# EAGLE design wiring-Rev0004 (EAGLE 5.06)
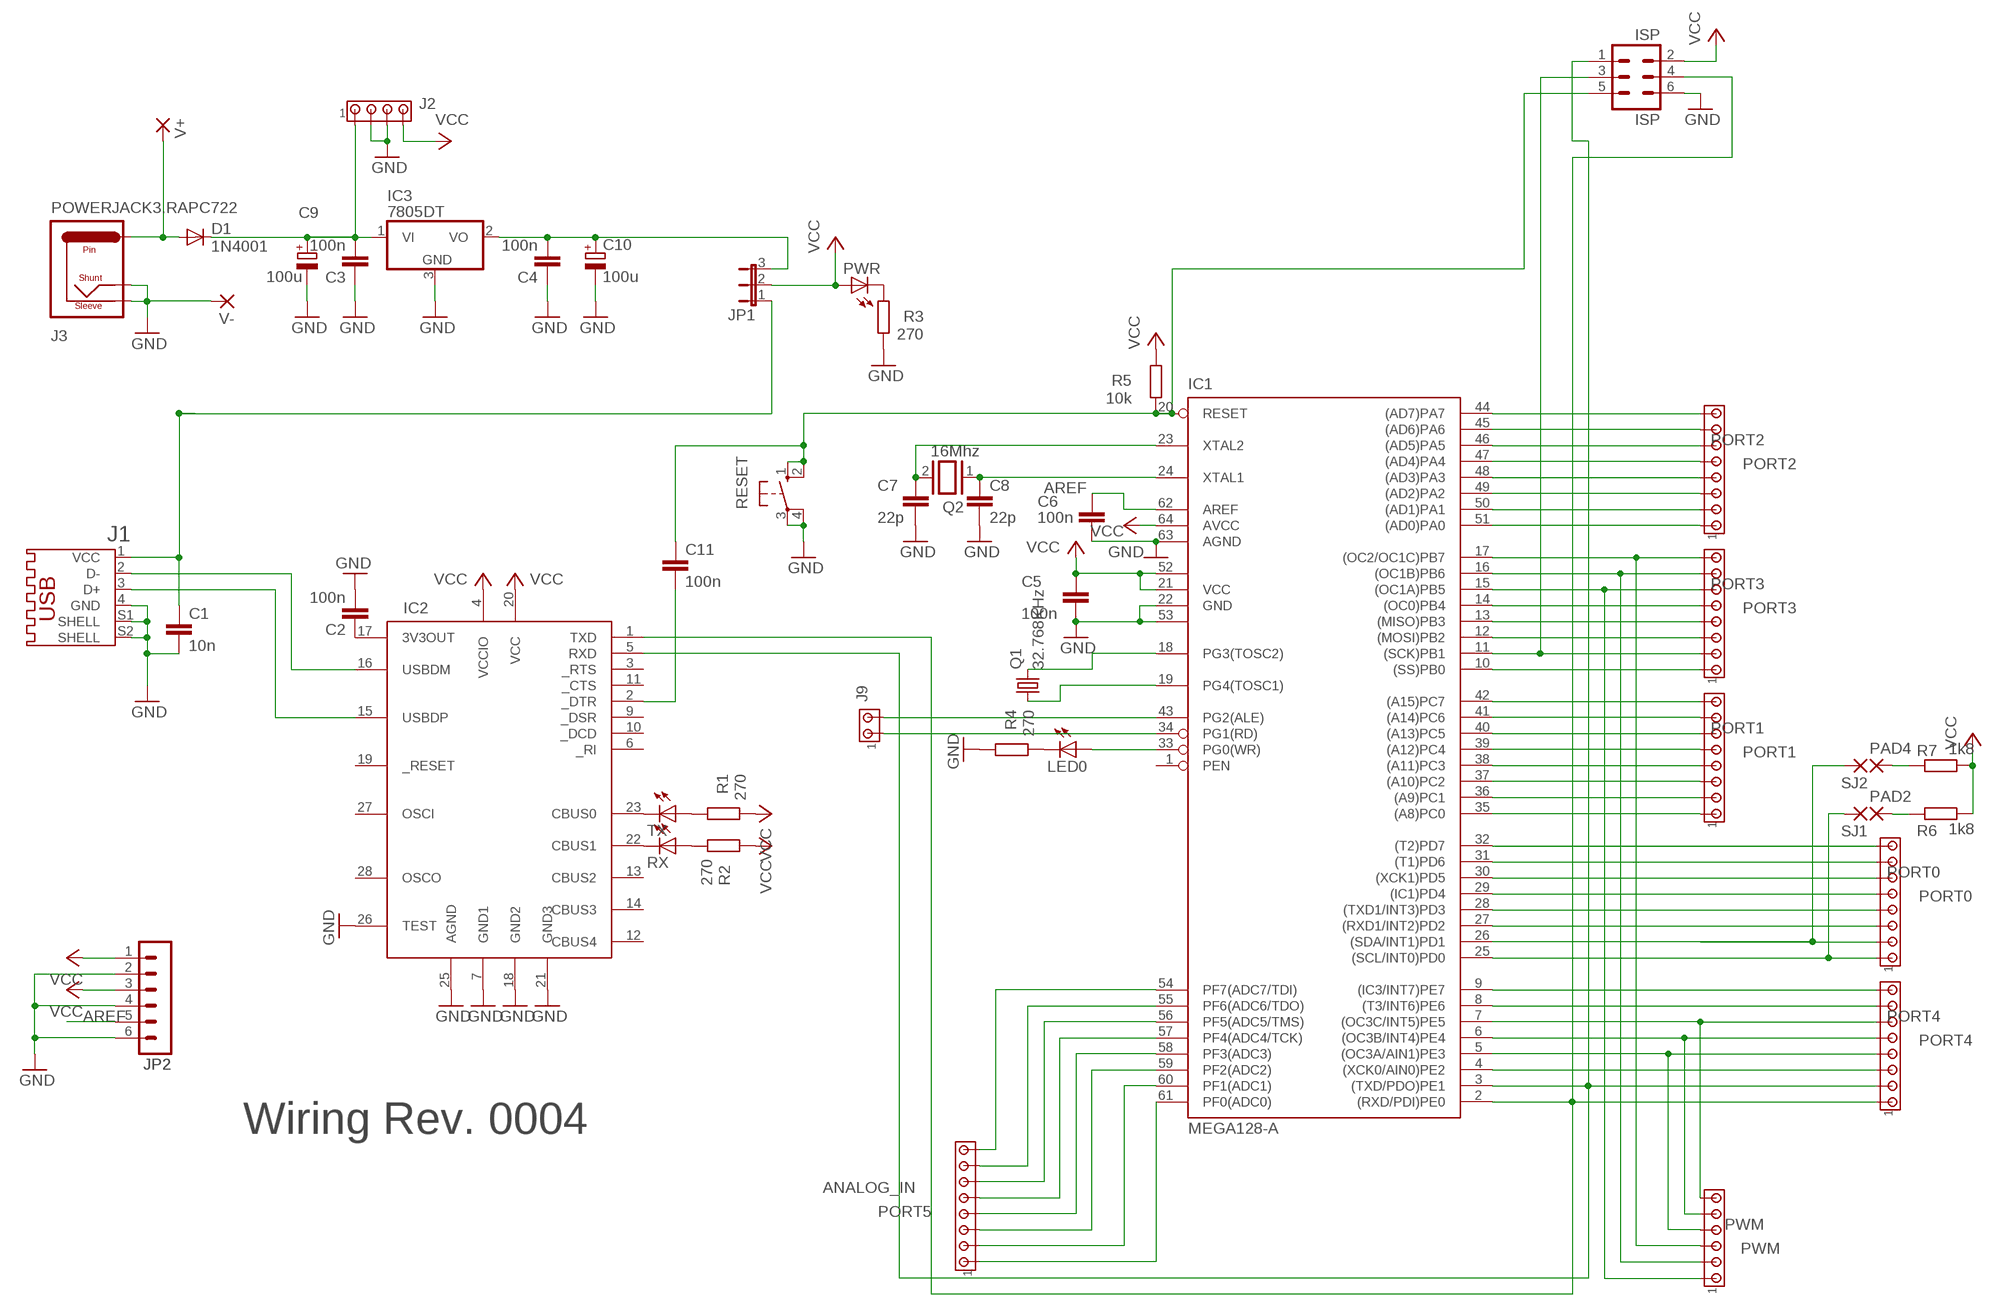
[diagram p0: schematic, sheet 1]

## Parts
ANALOG_IN  PORT5  MTA08-100  [10X08MTA]
C1  10n  C-EUC1206K  [C1206K]
C2  100n  C-EUC1206K  [C1206K]
C3  100n  C-EUC1206K  [C1206K]
C4  100n  C-EUC1206K  [C1206K]
C5  100n  C-EUC1206K  [C1206K]
C6  100n  C-EUC1206K  [C1206K]
C7  22p  C-EUC1206K  [C1206K]
C8  22p  C-EUC1206K  [C1206K]
C9  100u  CPOL-EU153CLV-0807  [153CLV-0807]
C10  100u  CPOL-EU153CLV-0807  [153CLV-0807]
C11  100n  C-EUC1206K  [C1206K]
D1  1N4001  DIODE-SOD106-R  [SOD106-R]
IC1  MEGA128-A  [TQFP64]
IC2  FT232RL  [SSOP28DB]
IC3  7805DT  [TO252]
ISP  ISP  MA03-2  [MA03-2]
J1  USB-CON-B  [USB-B-RECEPTACLE]
J2  MTA04-100  [10X04MTA]
J3  POWERJACK3.RAPC722  [SC.RAPC722]
J9  MTA02-100  [10X02MTA]
JP1  JP2E  [JP2]
JP2  MA06-1  [MA06-1]
LED0  LEDCHIPLED_1206  [CHIPLED_1206]
PAD2  1,6/0,8  [1,6/0,8]
PAD4  1,6/0,8  [1,6/0,8]
PORT0  PORT0  MTA08-100  [10X08MTA]
PORT1  PORT1  MTA08-100  [10X08MTA]
PORT2  PORT2  MTA08-100  [10X08MTA]
PORT3  PORT3  MTA08-100  [10X08MTA]
PORT4  PORT4  MTA08-100  [10X08MTA]
PWM  PWM  MTA06-100  [10X06MTA]
PWR  LEDCHIPLED_1206  [CHIPLED_1206]
Q1  32.768KHz  CRYTALMM20SS  [MM20SS]
Q2  16Mhz  XTAL/S  [QS]
R1  270  R-EU_R1206W  [R1206W]
R2  270  R-EU_R1206W  [R1206W]
R3  270  R-EU_R1206W  [R1206W]
R4  270  R-EU_R1206W  [R1206W]
R5  10k  R-EU_R1206W  [R1206W]
R6  1k8  R-EU_R1206W  [R1206W]
R7  1k8  R-EU_R1206W  [R1206W]
RESET  10-XX  [B3F-10XX]
RX  LEDCHIPLED_1206  [CHIPLED_1206]
SJ1  1,6/0,8  [1,6/0,8]
SJ2  1,6/0,8  [1,6/0,8]
TX  LEDCHIPLED_1206  [CHIPLED_1206]
V+  1,6/0,8  [1,6/0,8]
V-  1,6/0,8  [1,6/0,8]

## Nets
AREF: C6.1 IC1.62(AREF) JP2.5
GND: C1.2 C2.2 C3.1 C4.1 C5.2 C6.2 C7.2 C8.2 C9.- C10.- IC1.22(GND) IC1.53(GND1) IC1.63(AGND) IC2.7(GND1) IC2.18(GND2) IC2.21(GND3) IC2.25(AGND) IC2.26(TEST) IC3.3(GND) ISP.6 J1.4(GND) J1.S1(SHELL) J1.S2(SHELL) J2.2 J2.3 J3.SHUNT J3.SLEEVE JP2.2 JP2.4 JP2.6 R3.1 R4.2 RESET.3(P) RESET.4(P1) V-.1(P)
N$1: IC2.16(USBDM) J1.2(D-)
N$2: IC2.15(USBDP) J1.3(D+)
N$3: C2.1 IC2.17(3V3OUT)
N$4: IC2.23(CBUS0) TX.C
N$5: IC2.22(CBUS1) RX.C
N$6: R1.2 TX.A
N$7: C1.1 J1.1(VCC) JP1.1
N$8: R2.1 RX.A
N$9: PAD4.1(P) R7.2
N$10: PAD2.1(P) R6.2
N$11: C11.2 IC2.2(_DTR)
N$15: C7.1 IC1.23(XTAL2) Q2.2
N$16: C8.1 IC1.24(XTAL1) Q2.1
N$17: IC1.2((RXD/PDI)PE0) IC2.1(TXD) ISP.4 PORT4.1
N$18: IC1.3((TXD/PDO)PE1) IC2.5(RXD) ISP.1 PORT4.2
N$19: IC1.19(PG4(TOSC1)) Q1.1
N$21: IC1.51((AD0)PA0) PORT2.1
N$22: IC1.50((AD1)PA1) PORT2.2
N$23: IC1.49((AD2)PA2) PORT2.3
N$24: IC1.48((AD3)PA3) PORT2.4
N$25: IC1.47((AD4)PA4) PORT2.5
N$26: IC1.46((AD5)PA5) PORT2.6
N$27: IC1.45((AD6)PA6) PORT2.7
N$28: IC1.44((AD7)PA7) PORT2.8
N$29: IC1.14((OC0)PB4) PORT3.5
N$30: IC1.41((A14)PC6) PORT1.7
N$31: IC1.40((A13)PC5) PORT1.6
N$32: IC1.39((A12)PC4) PORT1.5
N$33: IC1.38((A11)PC3) PORT1.4
N$34: IC1.37((A10)PC2) PORT1.3
N$35: IC1.36((A9)PC1) PORT1.2
N$36: IC1.35((A8)PC0) PORT1.1
N$37: ANALOG_IN.1 IC1.61(PF0(ADC0))
N$38: ANALOG_IN.2 IC1.60(PF1(ADC1))
N$39: ANALOG_IN.3 IC1.59(PF2(ADC2))
N$40: ANALOG_IN.4 IC1.58(PF3(ADC3))
N$41: ANALOG_IN.5 IC1.57(PF4(ADC4/TCK))
N$42: ANALOG_IN.6 IC1.56(PF5(ADC5/TMS))
N$43: ANALOG_IN.7 IC1.55(PF6(ADC6/TDO))
N$44: ANALOG_IN.8 IC1.54(PF7(ADC7/TDI))
N$45: IC1.15((OC1A)PB5) PORT3.6 PWM.6
N$46: IC1.16((OC1B)PB6) PORT3.7 PWM.5
N$47: IC1.17((OC2/OC1C)PB7) PORT3.8 PWM.4
N$48: IC1.5((OC3A/AIN1)PE3) PORT4.4 PWM.3
N$49: IC1.6((OC3B/INT4)PE4) PORT4.5 PWM.2
N$50: IC1.7((OC3C/INT5)PE5) PORT4.6 PWM.1
N$51: IC1.25((SCL/INT0)PD0) PORT0.1 SJ1.1(P)
N$52: IC1.26((SDA/INT1)PD1) PORT0.2 SJ2.1(P)
N$54: D1.A J3.PIN V+.1(P)
N$56: C3.2 C9.+ D1.C IC3.1(VI) J2.1
N$57: PWR.C R3.2
N$58: IC1.13((MISO)PB3) PORT3.4
N$59: IC1.12((MOSI)PB2) PORT3.3
N$60: IC1.10((SS)PB0) PORT3.1
N$61: IC1.18(PG3(TOSC2)) Q1.4
N$62: IC1.33(PG0(WR)) LED0.A
N$63: IC1.11((SCK)PB1) ISP.3 PORT3.2
N$64: IC1.42((A15)PC7) PORT1.8
N$65: IC1.9((IC3/INT7)PE7) PORT4.8
N$66: IC1.27((RXD1/INT2)PD2) PORT0.3
N$67: IC1.28((TXD1/INT3)PD3) PORT0.4
N$68: IC1.29((IC1)PD4) PORT0.5
N$69: IC1.30((XCK1)PD5) PORT0.6
N$70: C11.1 IC1.20(RESET) ISP.5 R5.1 RESET.1(S) RESET.2(S1)
N$71: IC1.31((T1)PD6) PORT0.7
N$72: IC1.32((T2)PD7) PORT0.8
N$73: LED0.C R4.1
N$74: IC1.8((T3/INT6)PE6) PORT4.7
N$75: IC1.4((XCK0/AIN0)PE2) PORT4.3
N$76: IC1.43(PG2(ALE)) J9.2
N$77: IC1.34(PG1(RD)) J9.1
N$78: C4.2 C10.+ IC3.2(VO) JP1.3
VCC: C5.1 IC1.21(VCC) IC1.52(VCC1) IC1.64(AVCC) IC2.4(VCCIO) IC2.20(VCC) ISP.2 J2.4 JP1.2 JP2.1 JP2.3 PWR.A R1.1 R2.2 R5.2 R6.1 R7.1
Unconnected: IC1.1(PEN) IC2.3(_RTS) IC2.6(_RI) IC2.9(_DSR) IC2.10(_DCD) IC2.11(_CTS) IC2.12(CBUS4) IC2.13(CBUS2) IC2.14(CBUS3) IC2.19(_RESET) IC2.27(OSCI) IC2.28(OSCO)

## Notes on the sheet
- AREF
- AREF
- Wiring Rev. 0004

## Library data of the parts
ANALOG_IN PORT0 PORT1-PORT4 = con-amp:MTA08-100: AMP connector
C1-C8 C11 = rcl:C-EU: CAPACITOR, European symbol
C9 C10 = rcl:CPOL-EU: POLARIZED CAPACITOR, European symbol
D1 = diode:DIODE-: DIODE
IC1 = avr:MEGA128: MICROCONTROLLER 128 Kbytes FLASH 4 Kbytes SRAM 4 Kbytes EEPROM DUAL USART 8-channel 10 bit ADC
IC2 = ftdichip:FT232RL: USB UART 4th Generation USB UART (USB <-> Serial) Controller
IC3 = linear:78*: Positive VOLTAGE REGULATOR
ISP = con-lstb:MA03-2: PIN HEADER
J1 = usb:USB-CON: AMP Universal Serial Bus Connector 'B' Series
J2 = con-amp:MTA04-100: AMP connector
J3 = ads4:POWERJACK3: Pin-Sleeve-Shunt Power Jack
J9 = con-amp:MTA02-100: AMP connector
JP1 = jumper:JP2E: JUMPER
JP2 = con-lstb:MA06-1: PIN HEADER
LED0 PWR RX TX = led:LED: LED
PAD2 PAD4 SJ1 SJ2 V+ V- = wirepad:1,6/0,8: THROUGH-HOLE PAD
PWM = con-amp:MTA06-100: AMP connector
Q1 = crystal:CRYTAL: CRYSTAL
Q2 = special:XTAL/S: CRYSTAL
R1-R7 = rcl:R-EU_: RESISTOR, European symbol
RESET = switch-omron:10-XX: OMRON SWITCH

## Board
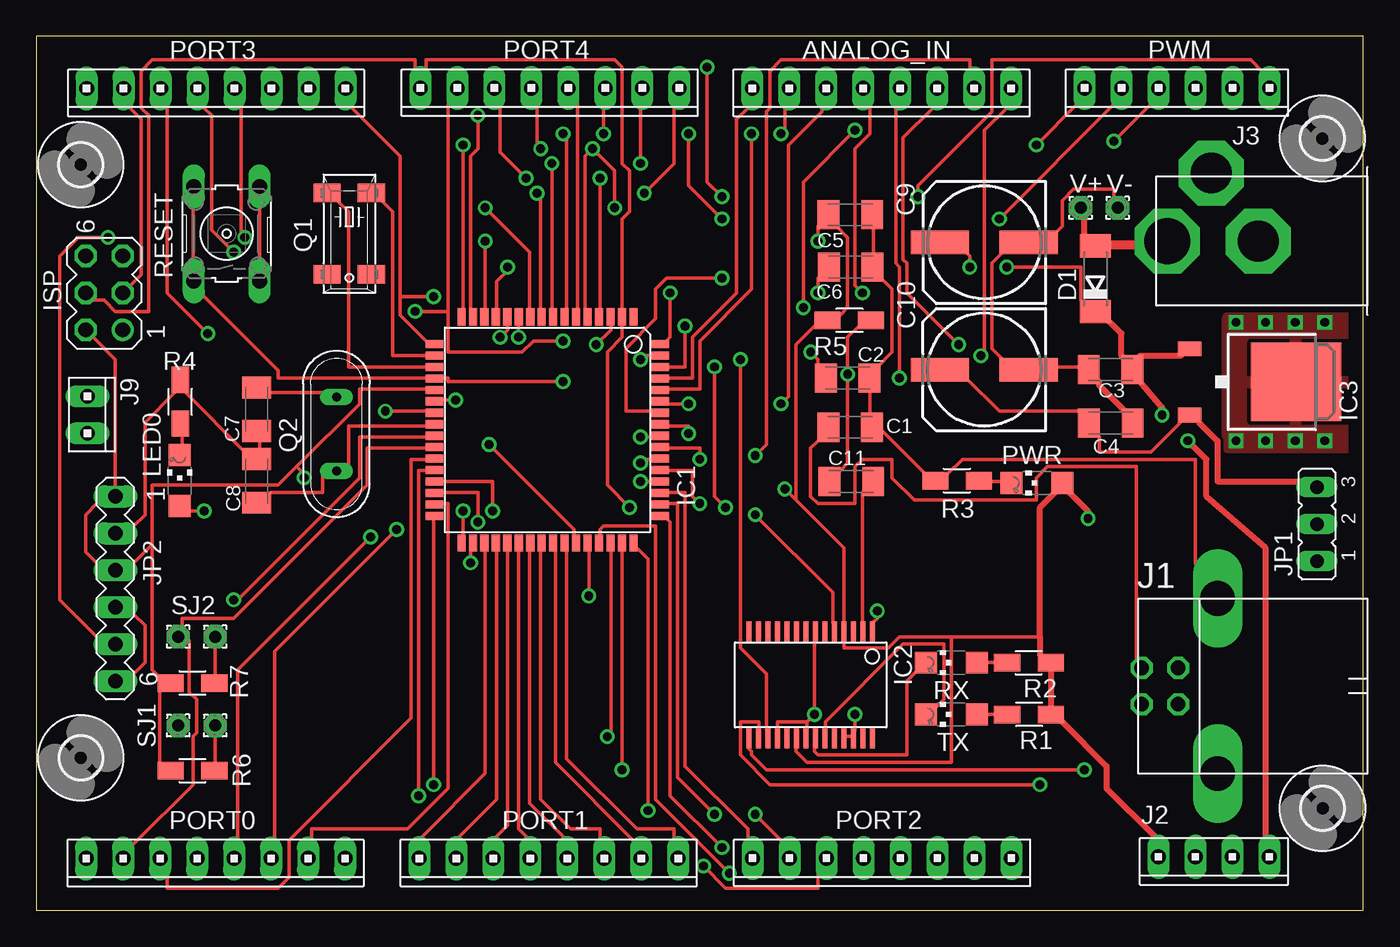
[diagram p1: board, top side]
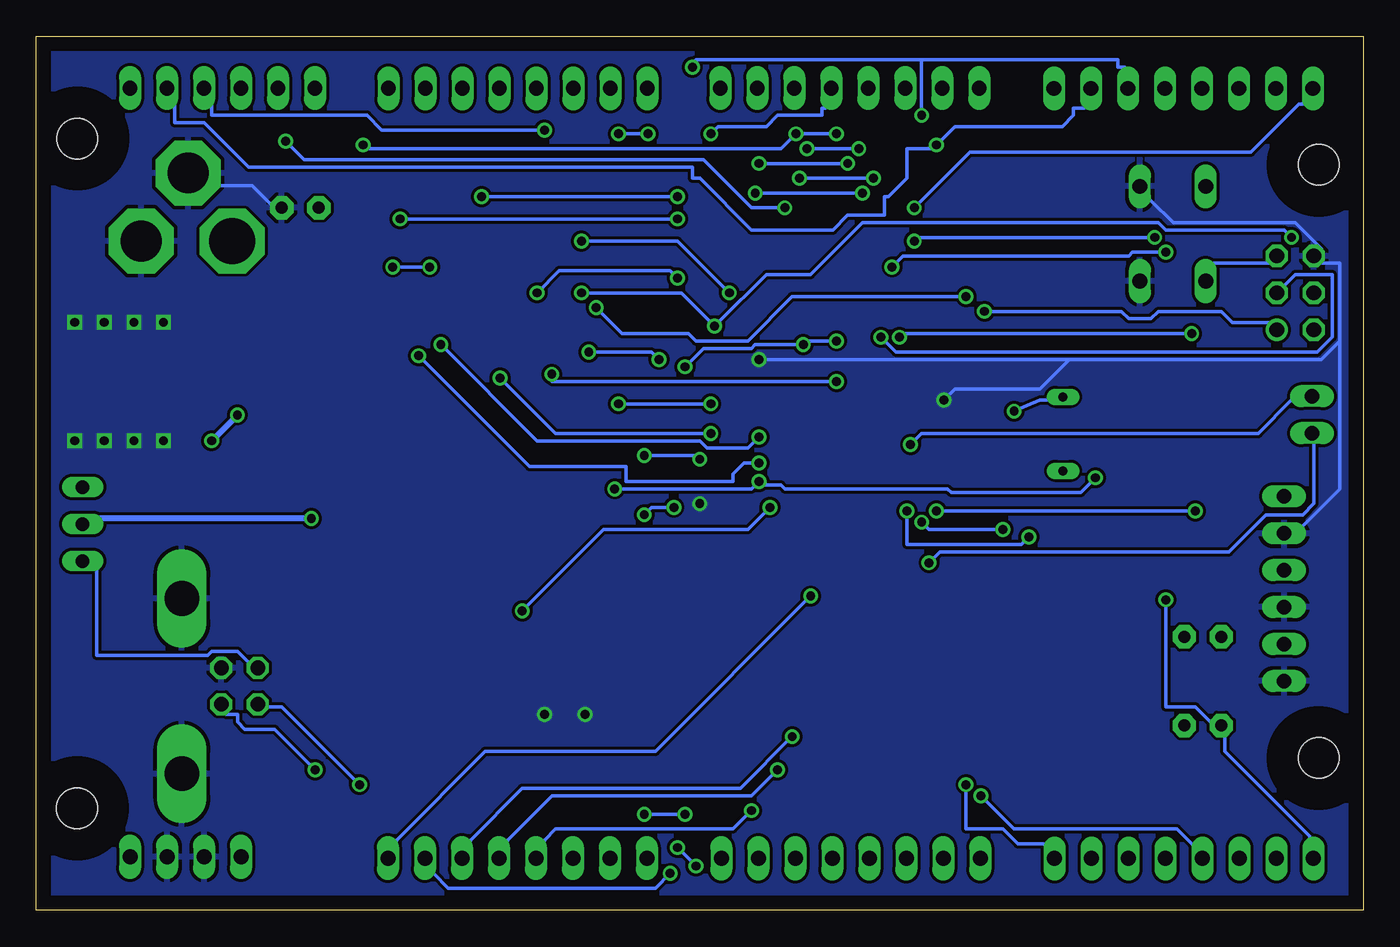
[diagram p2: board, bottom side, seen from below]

Size 91.11 x 60.03 mm. Coordinates in mm from the lower left corner, seen from the top.
Outline: 0,0 91.11,0 91.11,60.03 0,60.03 0,0
Copper layers (1*16): Top 0.035mm / dielectric 1.5mm / Bottom 0.035mm
Design rules "default": minimum track width 10mil, minimum drill 24mil, track to track 8mil, track to pad 8mil, pad to pad 8mil, via to via 8mil, smd to smd 8mil, copper to edge 40mil, drill to drill 8mil, minimum pad ring 10mil, minimum via ring 8mil, stop-mask expansion 4mil, vias tented up to drill 0mil, thermal gap 10mil
tRestrict: area 89.5,23.4 to 91,30.2; area 75.5,0 to 86.7,2
vRestrict: area 17.1,7.4 to 25.2,12.4; area 25.2,9.1 to 33.1,12.4; area 17.4,14.5 to 24.7,23.1; area 24.7,14.5 to 42.5,21.1; area 30.3,20.8 to 32.3,23.1; area 39,12.4 to 42.5,14.7; area 19.1,31 to 22.2,34.5

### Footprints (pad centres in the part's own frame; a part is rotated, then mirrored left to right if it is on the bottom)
10X08MTA = drill 1.016 long: 1 8.89,0; 2 6.35,0; 3 3.81,0; 4 1.27,0; 5 -1.27,0; 6 -3.81,0; 7 -6.35,0; 8 -8.89,0
C1206K = smd 1.5 x 2: 1 -1.5,0; 2 1.5,0
153CLV-0807 = smd 4 x 1.6: + 3.05,0; - -3.05,0
SOD106-R = smd 1.6 x 2.1: A 2.25,0; C -2.25,0
TQFP64 = smd 1.194 x 0.559: 1 -7.76,5.905; 2 -7.76,5.118; 3 -7.76,4.331; 4 -7.76,3.543; 5 -7.76,2.756; 6 -7.76,1.968; 7 -7.76,1.181; 8 -7.76,0.394; 9 -7.76,-0.394; 10 -7.76,-1.181; 11 -7.76,-1.968; 12 -7.76,-2.756; 13 -7.76,-3.543; 14 -7.76,-4.331; 15 -7.76,-5.118; 16 -7.76,-5.905; 33 7.76,-5.905; 34 7.76,-5.118; 35 7.76,-4.331; 36 7.76,-3.543; 37 7.76,-2.756; 38 7.76,-1.968; 39 7.76,-1.181; 40 7.76,-0.394; 41 7.76,0.394; 42 7.76,1.181; 43 7.76,1.968; 44 7.76,2.756; 45 7.76,3.543; 46 7.76,4.331; 47 7.76,5.118; 48 7.76,5.905 | smd 0.559 x 1.194: 17 -5.905,-7.76; 18 -5.118,-7.76; 19 -4.331,-7.76; 20 -3.543,-7.76; 21 -2.756,-7.76; 22 -1.968,-7.76; 23 -1.181,-7.76; 24 -0.394,-7.76; 25 0.394,-7.76; 26 1.181,-7.76; 27 1.968,-7.76; 28 2.756,-7.76; 29 3.543,-7.76; 30 4.331,-7.76; 31 5.118,-7.76; 32 5.905,-7.76; 49 5.905,7.76; 50 5.118,7.76; 51 4.331,7.76; 52 3.543,7.76; 53 2.756,7.76; 54 1.968,7.76; 55 1.181,7.76; 56 0.394,7.76; 57 -0.394,7.76; 58 -1.181,7.76; 59 -1.968,7.76; 60 -2.756,7.76; 61 -3.543,7.76; 62 -4.331,7.76; 63 -5.118,7.76; 64 -5.905,7.76
SSOP28DB = smd 0.348 x 1.397: 1 -4.225,-3.656; 2 -3.575,-3.656; 3 -2.925,-3.656; 4 -2.275,-3.656; 5 -1.625,-3.656; 6 -0.975,-3.656; 7 -0.325,-3.656; 8 0.325,-3.656; 9 0.975,-3.656; 10 1.625,-3.656; 11 2.275,-3.656; 12 2.925,-3.656; 13 3.575,-3.656; 14 4.225,-3.656; 15 4.225,3.656; 16 3.575,3.656; 17 2.925,3.656; 18 2.275,3.656; 19 1.625,3.656; 20 0.975,3.656; 21 0.325,3.656; 22 -0.325,3.656; 23 -0.975,3.656; 24 -1.625,3.656; 25 -2.275,3.656; 26 -2.925,3.656; 27 -3.575,3.656; 28 -4.225,3.656
TO252 = smd 1 x 1.6: 1 -2.28,-4.8; 2 2.28,-4.8 | smd 5.4 x 6.2: 3 0,2.5
MA03-2 = drill 1.016 round: 1 -2.54,-1.27 | drill 1.016 octagon: 2 -2.54,1.27; 3 0,-1.27; 4 0,1.27; 5 2.54,-1.27; 6 2.54,1.27
USB-B-RECEPTACLE = drill 1 octagon: 1 1.25,8.49; 2 -1.25,8.49; 3 -1.25,5.99; 4 1.25,5.99 | drill 2.38 long: S1 -6.02,3.28; S2 6.02,3.28
10X04MTA = drill 1.016 long: 1 -3.81,0; 2 -1.27,0; 3 1.27,0; 4 3.81,0
SC.RAPC722 = drill 3.175 pad 4.445 octagon: PIN 0,6.248 | drill 2.794 pad 4.445 octagon: SHUNT 4.674,3.226; SLEEVE 0,0
10X02MTA = drill 1.016 long: 1 1.27,0; 2 -1.27,0
JP2 = drill 0.914 long: 1 -2.54,0; 2 0,0; 3 2.54,0
MA06-1 = drill 1.016 long: 1 -6.35,0; 2 -3.81,0; 3 -1.27,0; 4 1.27,0; 5 3.81,0; 6 6.35,0
CHIPLED_1206 = smd 1.5 x 1.5: A 0,-1.75; C 0,1.75
1,6/0,8 = drill 0.813 pad 1.6 octagon: 1 0,0
10X06MTA = drill 1.016 long: 1 6.35,0; 2 3.81,0; 3 1.27,0; 4 -1.27,0; 5 -3.81,0; 6 -6.35,0
MM20SS = smd 1.27 x 1.88: 1 -2.794,-1.524; 2 2.794,-1.524; 3 2.794,1.524; 4 -2.794,1.524
QS = drill 0.61 long: 1 -2.54,0; 2 2.54,0
R1206W = smd 1.8 x 1.2: 1 -1.499,0; 2 1.499,0
B3F-10XX = drill 1.016 long: 1 -3.251,2.261; 2 3.251,2.261; 3 -3.251,-2.261; 4 3.251,-2.261
2,8 = hole 2.8: 0,0

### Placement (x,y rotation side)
ANALOG_IN  58.05,56.46 180 top
C1  55.89,33.18 0 top
C2  55.72,36.57 0 top
C3  73.76,37.15 0 top
C4  73.79,33.47 180 top
C5  55.89,47.77 0 top
C6  55.92,44.19 0 top
C7  15.14,34.42 270 top
C8  15.13,29.5 90 top
C9  65.1,45.87 180 top
C10  65.09,37.13 180 top
C11  55.97,29.46 0 top
D1  72.72,43.38 90 top
IC1  35.1,32.99 270 top
IC2  53.18,15.49 180 top
IC3  84,36.3 270 top
ISP  4.66,42.41 90 top
J1  84.4,15.4 90 top
J2  80.86,3.68 180 top
J3  83.91,45.97 90 top
J9  3.5,34.04 270 top
JP1  87.94,26.52 90 top
JP2  5.42,22.09 270 top
LED0  9.84,29.52 0 top
PAD2  12.28,12.69 0 top
PAD4  12.28,18.79 0 top
PORT0  12.31,3.57 180 top
PORT1  35.18,3.57 180 top
PORT2  58.07,3.58 180 top
PORT3  12.34,56.46 180 top
PORT4  35.25,56.48 180 top
PWM  78.33,56.48 180 top
PWR  68.7,29.35 90 top
Q1  21.49,46.48 270 top
Q2  20.61,32.73 90 top
R1  68.16,13.46 180 top
R2  68.16,17.01 0 top
R3  63.23,29.52 0 top
R4  9.88,34.94 90 top
R5  55.82,40.52 180 top
R6  10.73,9.6 0 top
R7  10.72,15.62 0 top
RESET  13.07,46.48 90 top
RX  62.83,17.01 90 top
SJ1  9.74,12.69 0 top
SJ2  9.74,18.79 0 top
TX  62.83,13.46 90 top
U$2  [2,8]  3.04,51.21 0 top
U$3  [2,8]  3.05,10.47 0 top
U$4  [2,8]  88.33,7.01 0 top
U$5  [2,8]  88.3,53.01 0 top
V+  71.72,48.25 0 top
V-  74.26,48.25 0 top

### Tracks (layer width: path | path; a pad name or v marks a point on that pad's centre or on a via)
AREF  (via drill 0.61)
  Top 0.254: v44.54,40.13 44.54,37.33 43.27,37.33 IC1.62 | v53.68,42.41 53.68,43.43 C6.1 | v4.92,46.22 2.88,46.22 1.61,44.95 1.61,21.33 4.15,18.79 JP2.5
  Bottom 0.254: v53.68,42.41 46.83,42.41 v44.54,40.13 44.29,40.38 40.98,43.68 37.94,43.68 34.38,47.24 14.06,47.24 13.55,46.73 5.42,46.73 v4.92,46.22
GND  (via drill 0.6, 0.61)
  Top 0.254: C7.2 15.33,32.25 15.33,31.75 C8.2 14.31,31.49 10.25,35.55 R4.2 9.49,35.55 7.46,33.52 7.46,27.17 6.69,26.41 JP2.2 | JP2.6 6.69,16.25 7.46,17.01 7.46,19.55 6.69,20.32 JP2.4 | RESET.3 15.33,44.7 15.33,48.25 RESET.4 | v28.79,35.05 27.78,35.05 IC1.22 | v41.49,37.84 41.49,38.09 42.51,38.09 IC1.63 | C3.1 71.72,37.33 69.94,37.33 C10.- 66.38,37.84 65.62,38.6 65.62,44.45 66.38,45.21 C9.- 69.94,46.48 70.45,46.98 70.45,48.76 71.21,49.52 74,49.52 74,49.02 V-.1 | 72.99,36.32 72.99,36.06 | C5.2 57.49,46.98 57.49,44.95 C6.2 58,43.43 58.76,42.67 58.76,38.35 57.75,37.33 C2.2 57.24,35.81 57.24,34.03 C1.2 58,33.02 61.05,29.97 R3.1 62.57,29.97 63.59,30.98 79.59,30.98 79.59,23.87 J1.S2 | 52.92,12.95 50.89,12.95 50.89,12.44 IC2.18 | 52.92,12.95 52.92,12.44 IC2.21 | 52.92,12.95 v53.43,13.46 53.43,18.54 IC2.7 | IC2.25 55.46,11.93 55.97,11.93 IC2.26 56.22,12.44 v56.22,13.46 | v45.55,27.94 45.05,28.44 45.05,30.22 43.27,30.22 IC1.53
  Top 0.406: 72.99,36.06 74.77,34.28 C4.1 | C3.1 72.99,36.32
  Bottom 0.254: v28.79,35.05 28.03,35.81 22.19,35.81 20.16,37.84 | 20.16,37.84 2.88,37.84 1.61,39.11 | 1.61,39.11 1.61,44.45 2.88,44.45 ISP.6 2.88,45.46 4.66,47.24 13.04,47.24 14.57,48.76 RESET.4 | 20.16,37.84 v41.49,37.84 | 1.61,39.11 1.61,28.95 4.15,26.41 JP2.2 | V-.1 75.02,48.51 76.29,49.78 78.57,49.78 J3.SHUNT
  other vias: 82.38,40.38 84.42,40.38 86.45,40.38 88.48,40.38 82.38,32.25 84.42,32.25 86.45,32.25 88.48,32.25
  pour Top: 81.83,40.7 90.03,40.7 90.03,39.89 90.03,31.8 81.83,31.8
  pour Bottom: 81.73,40.7 90.03,40.7 90.03,31.89 81.73,31.89
  pour Bottom: 0.34,59.68 90.51,59.68 90.51,0.25 0.34,0.25
N$1  (via drill 0.61)
  Top 0.254: v68.92,8.63 50.38,8.63 48.35,10.66 48.35,12.95 49.62,12.95 49.62,12.44 IC2.16
  Bottom 0.254: v68.92,8.63 74.26,13.96 75.27,13.96 J1.2
N$2  (via drill 0.61)
  Top 0.254: v71.97,9.65 50.13,9.65 49.11,10.66 49.11,10.92 48.86,11.17 IC2.15
  Bottom 0.254: v71.97,9.65 74.77,12.44 76.8,12.44 77.3,12.95 77.3,13.46 78.07,13.46 J1.3
N$3  (via drill 0.61)
  Top 0.254: v48.35,37.84 48.35,18.03 50.13,16.25 50.13,12.44 IC2.17 | v53.18,38.35 53.68,37.84 53.68,37.33 C2.1
  Bottom 0.254: v48.35,37.84 48.86,38.35 v53.18,38.35
N$4
  Top 0.254: IC2.23 54.19,12.44 54.19,12.95 59.52,18.28 62.32,18.28 62.32,14.47 61.81,13.96 TX.C
N$5
  Top 0.254: IC2.22 53.43,11.17 53.43,10.92 53.68,10.66 59.78,10.66 59.78,15.74 60.54,16.51 RX.C
N$6
  Top 0.254: TX.A 65.11,13.46 65.88,13.46 R1.2
N$7
  Top 0.254: C1.1 53.68,32.25 53.18,31.75 53.18,28.44 53.68,27.94 56.22,27.94 56.22,30.48 56.73,30.98 58.76,30.98 58.76,29.71 60.29,28.19 68.67,28.19 68.67,29.71 69.43,30.48 75.53,30.48 75.53,17.27 J1.1
  Bottom 0.254: JP1.1 86.96,23.36 86.96,17.52 79.34,17.52 79.08,17.78 77.3,17.78 76.54,17.01 J1.1
N$8
  Top 0.254: RX.A 65.11,17.01 65.88,17.01 R2.1
N$9
  Top 0.254: R7.2 12.28,16 12.28,18.03 PAD4.1
N$10
  Top 0.254: R6.2 12.28,10.15 12.28,11.93 PAD2.1
N$11
  Top 0.254: IC2.2 56.73,19.81 56.73,28.7 C11.2
N$15  (via drill 0.61)
  Top 0.254: v23.96,34.28 26.76,34.28 IC1.23 | C7.1 16.09,35.55 19.65,35.55 Q2.2
  Bottom 0.254: v23.96,34.28 22.19,35.05 21.68,35.05 Q2.2
N$16
  Top 0.254: IC1.24 26.76,33.27 21.43,33.27 21.43,30.48 Q2.1 19.65,29.97 19.65,28.7 16.09,28.7 C8.1
N$17  (via drill 0.61)
  Top 0.254: v57.75,20.57 57.75,20.06 57.49,19.81 IC2.1 | v40.73,27.68 39.2,29.21 39.2,38.35 40.22,39.36 40.22,40.38 IC1.2 40.22,41.14 40.22,47.49 40.73,48 40.73,50.79 40.22,51.3 40.22,57.91 39.71,58.41 26.76,58.41 26.76,57.91 PORT4.1 26,57.91 26,58.41 7.96,58.41 7.2,57.65 7.2,55.11 7.71,54.6 7.71,41.14 5.42,41.14 4.66,41.9 3.9,41.9 ISP.4
  Bottom 0.254: v57.75,20.57 52.16,26.16 42.25,26.16 v40.73,27.68
N$18  (via drill 0.61)
  Top 0.254: v38.44,38.86 39.46,39.87 39.46,40.38 IC1.3 | v36.16,39.11 34.12,39.11 33.36,38.35 28.28,38.35 28.28,41.14 | 28.28,41.14 28.28,55.37 PORT4.2 | v49.37,27.17 54.7,21.84 54.7,19.81 IC2.5 | v47.33,27.68 46.57,28.44 v46.57,37.33 | v26,41.14 28.28,41.14
  Bottom 0.254: v36.16,39.11 38.19,39.11 v38.44,38.86 38.7,38.86 41.74,38.86 42,38.6 45.3,38.6 v46.57,37.33 | v49.37,27.17 48.86,27.68 v47.33,27.68 | v26,41.14 16.6,41.14 16.09,40.63 14.57,40.63 14.06,41.14 9.74,41.14 8.98,40.38 6.44,40.38 ISP.1
N$19
  Top 0.254: IC1.19 26.76,37.33 21.43,37.33 21.43,48 20.66,48.76 Q1.1
N$21
  Top 0.254: IC1.51 43.27,28.7 44.54,28.7 44.54,9.9 48.86,5.58 48.86,5.08 PORT2.1
N$22  (via drill 0.61)
  Top 0.254: v46.57,6.6 44.03,9.14 44.03,27.94 43.27,27.94 IC1.50 | v49.37,6.6 51.14,4.82 PORT2.2
  Bottom 0.254: v46.57,6.6 v49.37,6.6
N$23  (via drill 0.61)
  Top 0.254: v47.08,4.31 43.52,7.87 43.52,26.67 43.27,26.92 IC1.49 | v45.81,3.04 47.33,1.52 53.68,1.52 53.68,2.54 PORT2.3
  Bottom 0.254: v45.81,3.04 v47.08,4.31
N$24  (via drill 0.61)
  Top 0.254: v42,6.85 42,24.12 41.24,24.89 IC1.48
  Bottom 0.254: v42,6.85 43.27,5.58 55.46,5.58 56.22,4.82 PORT2.4
N$25  (via drill 0.61)
  Top 0.254: v40.22,9.65 40.22,24.89 IC1.47
  Bottom 0.254: v40.22,9.65 42,7.87 55.72,7.87 58.76,4.82 PORT2.5
N$26  (via drill 0.61)
  Top 0.254: v39.2,11.93 39.46,12.19 39.46,24.89 IC1.46
  Bottom 0.254: v39.2,11.93 42.76,8.38 57.75,8.38 61.3,4.82 PORT2.6
N$27  (via drill 0.61)
  Top 0.254: v47.59,2.54 42.51,7.62 42.51,26.41 38.95,26.41 38.7,26.16 38.7,25.65 IC1.45
  Bottom 0.254: v47.59,2.54 48.6,1.52 62.83,1.52 63.84,2.54 PORT2.7
N$28  (via drill 0.61)
  Top 0.254: v37.94,21.59 37.94,24.89 IC1.44
  Bottom 0.254: v37.94,21.59 48.6,10.92 60.29,10.92 66.38,4.82 PORT2.8
N$29  (via drill 0.61)
  Top 0.254: v30.82,45.97 30.82,41.14 IC1.14 | v14.31,46.22 14.06,46.48 14.06,55.11 PORT3.5
  Bottom 0.254: v30.82,45.97 30.57,46.22 v14.31,46.22
N$30
  Top 0.254: IC1.41 35.65,24.89 35.65,10.15 40.98,4.82 PORT1.7
N$31
  Top 0.254: IC1.40 34.63,24.89 34.63,7.62 36.66,5.58 38.7,5.58 38.7,5.08 PORT1.6
N$32
  Top 0.254: IC1.39 33.87,24.89 33.87,7.36 36.16,5.08 PORT1.5
N$33
  Top 0.254: IC1.38 33.11,24.89 33.11,5.58 33.62,5.08 PORT1.4
N$34
  Top 0.254: IC1.37 32.35,24.89 32.35,5.84 31.59,5.08 PORT1.3
N$35
  Top 0.254: IC1.36 31.59,24.89 31.59,7.62 29.05,5.08 PORT1.2
N$36
  Top 0.254: IC1.35 30.82,24.89 30.82,9.39 26.51,5.08 PORT1.1
N$37
  Top 0.254: IC1.61 43.27,36.57 45.05,36.57 45.05,39.36 48.09,42.41 48.09,54.35 48.86,55.11 ANALOG_IN.1
N$38  (via drill 0.61)
  Top 0.254: v49.11,53.34 49.11,42.67 45.55,39.11 45.55,35.81 43.27,35.81 IC1.60 | v51.14,53.34 51.4,53.59 51.4,55.11 ANALOG_IN.2
  Bottom 0.254: v49.11,53.34 v51.14,53.34
N$39  (via drill 0.61)
  Top 0.254: v44.79,34.79 43.27,34.79 IC1.59 | v51.14,34.79 51.65,35.3 51.65,52.57 53.94,54.86 53.94,55.11 ANALOG_IN.3
  Bottom 0.254: v44.79,34.79 v51.14,34.79
N$40  (via drill 0.61)
  Top 0.254: v47.08,43.43 43.27,43.43 42.51,42.67 42.51,40.63 40.48,38.6 40.48,34.28 42.51,34.28 IC1.58 | v56.73,42.41 56.22,42.92 56.22,52.32 57.24,53.34 57.24,55.11 ANALOG_IN.4
  Bottom 0.254: v47.08,43.43 47.59,43.94 55.21,43.94 v56.73,42.41
N$41  (via drill 0.61)
  Top 0.254: v44.79,32.76 44.79,33.27 43.27,33.27 IC1.57 | v59.27,36.57 59.27,44.19 59.02,44.45 59.02,55.11 ANALOG_IN.5
  Bottom 0.254: v44.79,32.76 55.46,32.76 v59.27,36.57
N$42  (via drill 0.61)
  Top 0.254: v41.49,32.51 42.51,32.51 IC1.56 | v63.34,38.86 59.78,42.41 59.78,44.45 59.52,44.7 59.52,53.08 61.56,55.11 ANALOG_IN.6
  Bottom 0.254: v41.49,32.51 42.25,31.75 45.05,31.75 45.55,32.25 56.73,32.25 v63.34,38.86
N$43  (via drill 0.61)
  Top 0.254: v45.55,30.98 45.55,31.75 43.27,31.75 IC1.55 | v49.37,31.24 50.13,32 50.13,54.86 50.38,55.11 50.38,57.65 51.14,58.41 64.1,58.41 64.1,57.91 ANALOG_IN.7
  Bottom 0.254: v45.55,30.98 45.81,31.24 v49.37,31.24
N$44  (via drill 0.61)
  Top 0.254: v41.49,30.73 41.49,30.98 42.51,30.98 IC1.54 | v64.86,38.09 65.11,38.35 65.11,53.59 66.64,55.11 ANALOG_IN.8
  Bottom 0.254: v41.49,30.73 42.51,30.73 43.27,29.97 43.27,29.46 50.63,29.46 50.63,30.48 57.24,30.48 v64.86,38.09
N$45  (via drill 0.61)
  Top 0.254: v60.54,49.02 60.54,49.78 65.62,54.86 65.62,58.41 83.4,58.41 84.16,57.65 PWM.6 | v47.08,49.02 46.06,50.03 v46.06,57.91 | v30.32,54.6 30.32,52.32 29.81,51.81 29.81,41.14 IC1.15
  Bottom 0.254: v47.08,49.02 v60.54,49.02 | v46.06,57.91 45.81,58.16 45.81,58.41 30.32,58.41 | 30.32,58.41 16.85,58.41 16.85,57.91 16.35,57.91 PORT3.6 | v30.32,54.6 30.32,58.41
N$46  (via drill 0.61)
  Top 0.254: v29.3,52.57 29.3,41.14 IC1.16
  Bottom 0.254: PORT3.7 19.14,55.11 19.9,55.11 19.9,54.6 20.66,53.84 28.03,53.84 v29.3,52.57 29.55,52.32 31.33,52.32 31.33,50.29 32.6,49.02 32.86,49.02 32.86,47.75 35.4,47.75 36.41,46.73 42,46.73 45.55,50.29 46.06,50.29 46.06,51.05 76.54,51.05 79.59,54.1 81.62,54.1 81.62,55.37 PWM.5
N$47  (via drill 0.61)
  Top 0.254: 24.98,42.16 24.98,51.81 21.68,55.11 PORT3.8 | 24.98,42.16 24.98,40.89 26.76,39.11 IC1.17 | v56.22,53.59 52.67,50.03 v52.67,41.4 | 24.98,42.16 v27.27,42.16
  Bottom 0.254: v56.22,53.59 67.4,53.59 68.41,54.6 79.08,54.6 79.08,55.37 PWM.4 | v52.67,41.4 50.89,39.62 46.32,39.62 45.81,39.11 42.25,39.11 39.2,42.16 v27.27,42.16
N$48  (via drill 0.61)
  Top 0.254: v34.63,52.32 34.38,52.57 34.38,55.11 PORT4.4 | IC1.5 37.68,41.14 37.68,51.81 v38.19,52.32 38.44,52.06 39.71,50.79 v39.71,48.25 | v74,52.83 76.54,55.37 PWM.3
  Bottom 0.254: v38.19,52.32 v34.63,52.32 | v74,52.83 72.73,51.56 45.3,51.56 42,48.25 v39.71,48.25
N$49  (via drill 0.61)
  Top 0.254: IC1.6 37.17,41.14 37.17,55.37 PORT4.5 | v66.13,47.49 74,55.37 PWM.2 | v47.08,47.49 44.79,49.78 v44.79,53.34
  Bottom 0.254: v47.08,47.49 v66.13,47.49 | v44.79,53.34 44.29,53.84 40.98,53.84 40.22,54.6 37.17,54.6 37.17,55.11 36.92,55.11 PORT4.5
N$50  (via drill 0.61)
  Top 0.254: v36.16,53.34 36.41,53.08 36.41,41.14 IC1.7 | v38.95,53.34 38.95,55.11 PORT4.6 | v68.67,52.57 71.46,55.37 PWM.1
  Bottom 0.254: v36.16,53.34 v38.95,53.34 39.2,53.08 39.97,52.32 68.41,52.32 v68.67,52.57
N$51  (via drill 0.61)
  Top 0.254: v13.55,21.33 13.81,21.33 22.19,29.71 22.19,32.51 26.76,32.51 IC1.25
  Bottom 0.254: v13.55,21.33 13.55,13.96 11.52,13.96 10.5,12.95 SJ1.1 9.49,11.93 9.49,10.92 3.65,5.08 PORT0.1
N$52
  Top 0.254: IC1.26 26.76,31.75 22.7,31.75 22.7,29.21 13.55,20.06 10,20.06 10,19.55 SJ2.1 10.5,18.54 10.5,14.98 11.01,14.47 11.01,12.19 10.76,11.93 10.76,8.63 6.69,4.57 PORT0.2
N$54
  Top 0.254: 71.97,46.22 D1.A 73.75,45.71
  Top 0.406: 71.97,46.22 71.97,47.49 V+.1
  Top 0.61: 73.75,45.71 75.53,45.71 J3.PIN
N$56  (via drill 0.61)
  Top 0.254: 75.78,36.32 C3.2 | v64.1,44.19 64.1,44.95 63.84,45.21 C9.+ | v66.64,44.19 71.72,44.19 71.72,41.9 D1.C
  Top 0.406: D1.C 73.75,40.38 74.51,39.62 74.51,38.09 C3.2 75.78,38.09 78.57,38.09 IC3.1 | 75.78,36.32 77.3,34.54 v77.3,34.03 | v79.08,32.25 80.35,30.98 80.35,28.44 84.42,24.89 84.42,5.08 J2.1
  Bottom 0.254: v66.64,44.19 v64.1,44.19
  Bottom 0.406: v79.08,32.25 v77.3,34.03
N$57
  Top 0.254: PWR.C 66.38,29.46 65.62,29.46 R3.2
N$58  (via drill 0.61)
  Top 0.254: v32.35,44.19 32.35,43.94 31.59,43.17 31.59,41.14 IC1.13 | v13.55,45.21 12.03,46.73 12.03,54.6 11.52,55.11 PORT3.4
  Bottom 0.254: v32.35,44.19 31.59,44.95 16.09,44.95 15.84,45.21 v13.55,45.21
N$59  (via drill 0.61)
  Top 0.254: v31.84,39.36 32.35,39.87 32.35,40.38 IC1.12 | v11.77,39.62 8.98,42.41 8.98,55.11 PORT3.3
  Bottom 0.254: v31.84,39.36 31.59,39.62 v11.77,39.62
N$60  (via drill 0.61)
  Top 0.254: v30.82,48.25 33.87,45.21 33.87,41.14 IC1.10
  Bottom 0.254: v30.82,48.25 27.01,52.06 7.71,52.06 4.41,55.37 4.15,55.37 PORT3.1
N$61
  Top 0.254: IC1.18 26.76,38.09 24.47,38.09 24.47,48 23.71,48.76 Q1.4
N$62  (via drill 0.61)
  Top 0.254: v29.3,27.43 29.3,25.65 IC1.33 | v11.52,27.43 10.5,27.43 LED0.A
  Bottom 0.254: v11.52,27.43 v29.3,27.43
N$63  (via drill 0.61)
  Top 0.254: v33.11,39.36 33.11,40.38 IC1.11 | PORT3.2 6.44,55.11 7.2,54.35 7.2,43.68 6.44,42.92 ISP.3
  Bottom 0.254: v33.11,39.36 32.09,38.35 3.14,38.35 2.12,39.36 2.12,43.68 4.66,43.68 5.42,42.92 ISP.3
N$64
  Top 0.254: IC1.42 36.41,24.89 36.41,10.41 41.24,5.58 43.78,5.58 43.78,5.08 PORT1.8
N$65  (via drill 0.61)
  Top 0.254: v34.38,49.27 34.63,49.02 34.63,41.14 IC1.9 | v41.74,49.27 43.78,51.3 43.78,55.11 PORT4.8
  Bottom 0.254: v34.38,49.27 v41.74,49.27
N$66
  Top 0.254: IC1.27 26.76,30.98 25.74,30.98 25.74,13.2 17.36,4.82 17.36,2.28 16.6,1.52 8.98,1.52 8.98,2.28 PORT0.3
N$67  (via drill 0.61)
  Top 0.254: v26.25,7.87 26.25,30.22 26.76,30.22 IC1.28
  Bottom 0.254: v26.25,7.87 23.96,5.58 12.79,5.58 11.77,4.57 PORT0.4
N$68  (via drill 0.61)
  Top 0.254: v31.33,27.43 31.33,29.46 27.78,29.46 IC1.29 | v22.95,25.65 13.81,16.51 13.81,5.08 PORT0.5
  Bottom 0.254: v31.33,27.43 31.33,25.14 23.46,25.14 v22.95,25.65
N$69  (via drill 0.61)
  Top 0.254: v30.32,26.67 30.32,28.7 27.78,28.7 IC1.30 | v24.73,26.16 16.35,17.78 16.35,5.08 PORT0.6
  Bottom 0.254: v30.32,26.67 29.81,26.16 v24.73,26.16
N$70  (via drill 0.61)
  Top 0.254: RESET.2 10.76,48.25 10.76,44.7 RESET.1 11.52,42.16 16.6,37.08 16.6,36.57 26.76,36.57 IC1.20 27.78,36.57 28.28,36.57 28.28,36.32 v36.16,36.32 | R5.1 56.48,40.13 55.72,39.36 v55.72,36.82 55.72,30.73 55.21,30.22 C11.1
  Bottom 0.254: ISP.5 6.44,44.45 10.25,44.45 RESET.1 | v55.72,36.82 55.72,36.32 v36.16,36.32
N$71
  Top 0.254: IC1.31 27.78,27.94 28.28,27.94 28.28,8.38 25.49,5.58 18.89,5.58 18.89,5.08 PORT0.7
N$72  (via drill 0.61)
  Top 0.254: v27.27,8.63 27.27,26.92 IC1.32
  Bottom 0.254: v27.27,8.63 27.27,5.58 24.73,5.58 23.71,4.57 21.93,4.57 PORT0.8
N$73
  Top 0.254: LED0.C 10,32 10,32.76 R4.1
N$74  (via drill 0.61)
  Top 0.254: v35.4,51.3 35.4,41.14 IC1.8 | v41.49,51.3 41.49,55.11 PORT4.7
  Bottom 0.254: v35.4,51.3 v41.49,51.3
N$75  (via drill 0.61)
  Top 0.254: v38.7,50.29 38.7,41.14 IC1.4 | v33.62,50.29 31.84,52.06 31.84,55.11 PORT4.3
  Bottom 0.254: v38.7,50.29 v33.62,50.29
N$76  (via drill 0.61)
  Top 0.254: v31.08,32 36.92,26.16 36.92,25.65 IC1.43
  Bottom 0.254: v31.08,32 30.32,32.76 7.2,32.76 4.92,35.05 J9.2
N$77  (via drill 0.61)
  Top 0.254: v29.81,23.87 29.81,24.89 IC1.34
  Bottom 0.254: v29.81,23.87 29.05,24.63 9.23,24.63 6.69,27.17 4.15,27.17 3.39,27.94 3.39,32.25 J9.1
N$78
  Top 0.254: C10.+ 63.84,36.57 66.13,34.28 71.72,34.28 C4.2 72.99,32.51 72.99,31.49 76.54,31.49 78.57,33.52 IC3.2 79.84,33.52
  Top 0.406: 79.84,33.52 81.11,32.25 81.11,29.46 86.7,29.46 JP1.3
VCC  (via drill 0.61)
  Top 0.254: R6.1 8.47,10.15 8.47,15.23 R7.1 8.47,16 7.96,16.51 7.96,25.14 | 17.87,30.48 16.6,29.21 7.96,29.21 7.96,25.14 | 17.87,30.48 22.19,34.79 22.19,35.81 26.76,35.81 IC1.21 | 7.96,25.14 6.69,23.87 JP2.3 4.15,23.87 3.39,24.63 3.39,27.17 4.15,27.94 JP2.1 5.42,28.95 5.42,37.84 3.9,39.36 ISP.2 | 62.83,18.79 59.27,18.79 58.51,18.03 55.46,18.03 55.46,18.54 IC2.4 55.46,19.81 55.46,24.89 52.16,28.19 | 62.83,18.79 68.92,18.79 | 68.92,17.52 R2.2 69.68,16.51 | 69.94,28.7 PWR.A | 69.68,13.96 R1.1 | 62.83,18.79 62.83,10.15 52.92,10.15 52.16,10.92 52.16,11.17 IC2.20 | v43.52,42.41 43.52,39.36 43.27,39.11 IC1.64 | v53.68,45.97 53.68,46.98 C5.1 54.95,46.98 55.72,46.22 55.72,41.4 55.21,40.89 R5.2 53.43,40.13 52.16,38.86 52.16,28.19 | v41.49,29.46 42.51,29.46 IC1.52 | v51.4,28.95 52.16,28.19 | 17.87,30.48 18.38,29.97 v18.38,29.71
  Top 0.406: 68.92,17.52 68.92,18.79 68.92,27.68 69.94,28.7 | 69.68,16.51 69.68,13.96 | J2.4 76.8,5.08 73.49,8.38 73.49,9.9 70.45,12.95 R1.1 | v72.22,26.92 72.22,27.43 70.95,28.7 PWR.A
  Bottom 0.254: v43.52,42.41 47.08,45.97 v53.68,45.97 | v51.4,28.95 42,28.95 v41.49,29.46 41.24,29.21 39.97,29.21 39.71,28.95 28.54,28.95 28.28,28.7 19.39,28.7 v18.38,29.71
  Bottom 0.406: JP1.2 87.54,26.92 v72.22,26.92

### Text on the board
tDocu: 24 | 31 | 32 | 39 | 0 | 7 | 0 | 5 | Rx | Tx | 50 | 49 | 48 | vcc | GND | vcc | GND | AREF | GND | wiring.org.co | Hernando Barragán | Rev 0004 | SCL | SDA | vcc | GND | GND | 9-13v | 0 | Rx | Tx | 7 | 8 | 15 | 16 | 23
